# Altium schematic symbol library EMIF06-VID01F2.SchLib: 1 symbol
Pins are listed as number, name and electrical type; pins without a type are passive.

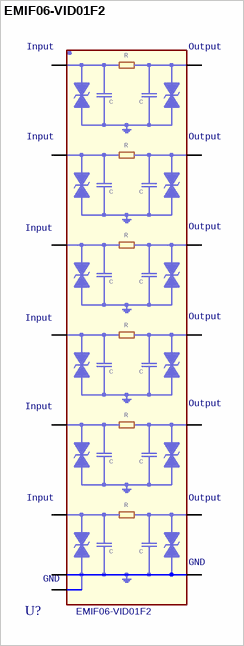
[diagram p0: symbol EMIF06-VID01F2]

## EMIF06-VID01F2
designator U?
footprint ST_CSP15N43P3X9_292X129X65
pins: A1 Input1, A3 Input2, A4 Input3, A6 Input4, A7 Input5, A9 Input6, B2 GND, B5 GND1, B8 GND2, C1 Output1, C3 Output2, C4 Output3, C6 Output4, C7 Output5, C9 Output6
